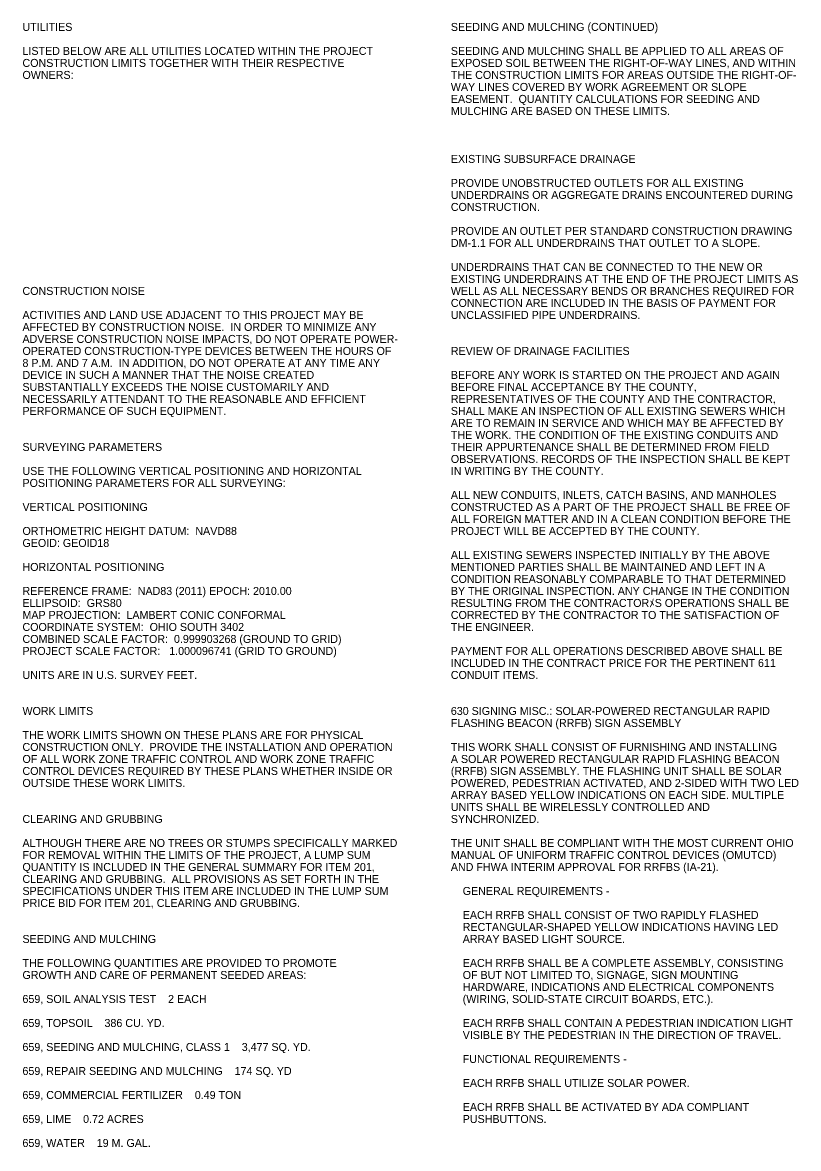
# Model space of a CAD drawing. Extents: x -8.5 to 44.5, y -30.9 to 22.
# Drawn here: x 1.43 to 15.02, y -30.07 to -10.36 of the extents above; entities that cross this region are included whole.
import ezdxf

# ---------------------------------------------------------------- set-up
doc = ezdxf.new("R2010")
doc.units = 0
doc.layers.add('SV_X_Random_Point', color=7, linetype='Continuous')

msp = doc.modelspace()

# ---------------------------------------------------------------- texts
at = {"layer": 'SV_X_Random_Point'}
for s, p in [('UTILITIES', (1.431, -10.511)), ('SEEDING AND MULCHING (CONTINUED)', (8.931, -10.511)), ('LISTED BELOW ARE ALL UTILITIES LOCATED WITHIN THE PROJECT ', (1.431, -10.931)), ('SEEDING AND MULCHING SHALL BE APPLIED TO ALL AREAS OF ', (8.931, -10.931)), ('CONSTRUCTION LIMITS TOGETHER WITH THEIR RESPECTIVE ', (1.431, -11.141)), ('EXPOSED SOIL BETWEEN THE RIGHT-OF-WAY LINES, AND WITHIN ', (8.931, -11.141)), ('OWNERS:', (1.431, -11.351)), ('THE CONSTRUCTION LIMITS FOR AREAS OUTSIDE THE RIGHT-OF-', (8.931, -11.351)), ('WAY LINES COVERED BY WORK AGREEMENT OR SLOPE ', (8.931, -11.561)), ('EASEMENT.  QUANTITY CALCULATIONS FOR SEEDING AND ', (8.931, -11.771)), ('MULCHING ARE BASED ON THESE LIMITS.', (8.931, -11.981)), ('EXISTING SUBSURFACE DRAINAGE', (8.931, -12.821)), ('PROVIDE UNOBSTRUCTED OUTLETS FOR ALL EXISTING ', (8.931, -13.241)), ('UNDERDRAINS OR AGGREGATE DRAINS ENCOUNTERED DURING ', (8.931, -13.451)), ('CONSTRUCTION.', (8.931, -13.661)), ('PROVIDE AN OUTLET PER STANDARD CONSTRUCTION DRAWING ', (8.931, -14.081)), ('DM-1.1 FOR ALL UNDERDRAINS THAT OUTLET TO A SLOPE.', (8.931, -14.291)), ('UNDERDRAINS THAT CAN BE CONNECTED TO THE NEW OR ', (8.931, -14.711)), ('EXISTING UNDERDRAINS AT THE END OF THE PROJECT LIMITS AS ', (8.931, -14.921)), ('CONSTRUCTION NOISE', (1.431, -15.131)), ('WELL AS ALL NECESSARY BENDS OR BRANCHES REQUIRED FOR ', (8.931, -15.131)), ('CONNECTION ARE INCLUDED IN THE BASIS OF PAYMENT FOR ', (8.931, -15.341)), ('ACTIVITIES AND LAND USE ADJACENT TO THIS PROJECT MAY BE ', (1.431, -15.551)), ('UNCLASSIFIED PIPE UNDERDRAINS.', (8.931, -15.551)), ('AFFECTED BY CONSTRUCTION NOISE.  IN ORDER TO MINIMIZE ANY ', (1.431, -15.761)), ('ADVERSE CONSTRUCTION NOISE IMPACTS, DO NOT OPERATE POWER-', (1.431, -15.971)), ('OPERATED CONSTRUCTION-TYPE DEVICES BETWEEN THE HOURS OF ', (1.431, -16.181)), ('REVIEW OF DRAINAGE FACILITIES', (8.931, -16.181)), ('8 P.M. AND 7 A.M.  IN ADDITION, DO NOT OPERATE AT ANY TIME ANY ', (1.431, -16.391)), ('DEVICE IN SUCH A MANNER THAT THE NOISE CREATED ', (1.431, -16.601)), ('BEFORE ANY WORK IS STARTED ON THE PROJECT AND AGAIN ', (8.931, -16.601)), ('SUBSTANTIALLY EXCEEDS THE NOISE CUSTOMARILY AND ', (1.431, -16.811)), ('BEFORE FINAL ACCEPTANCE BY THE COUNTY, ', (8.931, -16.811)), ('NECESSARILY ATTENDANT TO THE REASONABLE AND EFFICIENT ', (1.431, -17.021)), ('REPRESENTATIVES OF THE COUNTY AND THE CONTRACTOR, ', (8.931, -17.021)), ('PERFORMANCE OF SUCH EQUIPMENT.', (1.431, -17.231)), ('SHALL MAKE AN INSPECTION OF ALL EXISTING SEWERS WHICH ', (8.931, -17.231)), ('ARE TO REMAIN IN SERVICE AND WHICH MAY BE AFFECTED BY ', (8.931, -17.441)), ('THE WORK. THE CONDITION OF THE EXISTING CONDUITS AND ', (8.931, -17.651)), ('SURVEYING PARAMETERS', (1.431, -17.861)), ('THEIR APPURTENANCE SHALL BE DETERMINED FROM FIELD ', (8.931, -17.861)), ('OBSERVATIONS. RECORDS OF THE INSPECTION SHALL BE KEPT ', (8.931, -18.071)), ('USE THE FOLLOWING VERTICAL POSITIONING AND HORIZONTAL ', (1.431, -18.281)), ('IN WRITING BY THE COUNTY.', (8.931, -18.281)), ('POSITIONING PARAMETERS FOR ALL SURVEYING:', (1.431, -18.491)), ('ALL NEW CONDUITS, INLETS, CATCH BASINS, AND MANHOLES ', (8.931, -18.701)), ('VERTICAL POSITIONING', (1.431, -18.911)), ('CONSTRUCTED AS A PART OF THE PROJECT SHALL BE FREE OF ', (8.931, -18.911)), ('ALL FOREIGN MATTER AND IN A CLEAN CONDITION BEFORE THE ', (8.931, -19.121)), ('ORTHOMETRIC HEIGHT DATUM:  NAVD88 ', (1.431, -19.331)), ('PROJECT WILL BE ACCEPTED BY THE COUNTY.', (8.931, -19.331)), ('GEOID: GEOID18', (1.431, -19.541)), ('ALL EXISTING SEWERS INSPECTED INITIALLY BY THE ABOVE ', (8.931, -19.751)), ('HORIZONTAL POSITIONING', (1.431, -19.961)), ('MENTIONED PARTIES SHALL BE MAINTAINED AND LEFT IN A ', (8.931, -19.961)), ('CONDITION REASONABLY COMPARABLE TO THAT DETERMINED ', (8.931, -20.171)), ('REFERENCE FRAME:  NAD83 (2011) EPOCH: 2010.00', (1.431, -20.381)), ('BY THE ORIGINAL INSPECTION. ANY CHANGE IN THE CONDITION ', (8.931, -20.381)), ('ELLIPSOID:  GRS80', (1.431, -20.591)), ('RESULTING FROM THE CONTRACTORﾒS OPERATIONS SHALL BE ', (8.931, -20.591)), ('MAP PROJECTION:  LAMBERT CONIC CONFORMAL', (1.431, -20.801)), ('CORRECTED BY THE CONTRACTOR TO THE SATISFACTION OF ', (8.931, -20.801)), ('COORDINATE SYSTEM:  OHIO SOUTH 3402', (1.431, -21.011)), ('THE ENGINEER.', (8.931, -21.011)), ('COMBINED SCALE FACTOR:  0.999903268 (GROUND TO GRID)', (1.431, -21.221)), ('PROJECT SCALE FACTOR:   1.000096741 (GRID TO GROUND)', (1.431, -21.431)), ('PAYMENT FOR ALL OPERATIONS DESCRIBED ABOVE SHALL BE ', (8.931, -21.431)), ('INCLUDED IN THE CONTRACT PRICE FOR THE PERTINENT 611 ', (8.931, -21.641)), ('UNITS ARE IN U.S. SURVEY FEET.', (1.431, -21.851)), ('CONDUIT ITEMS.', (8.931, -21.851)), ('WORK LIMITS', (1.431, -22.481)), ('630 SIGNING MISC.: SOLAR-POWERED RECTANGULAR RAPID', (8.931, -22.481)), ('FLASHING BEACON (RRFB) SIGN ASSEMBLY', (8.931, -22.691)), ('THE WORK LIMITS SHOWN ON THESE PLANS ARE FOR PHYSICAL ', (1.431, -22.901)), ('CONSTRUCTION ONLY.  PROVIDE THE INSTALLATION AND OPERATION ', (1.431, -23.111)), ('THIS WORK SHALL CONSIST OF FURNISHING AND INSTALLING', (8.931, -23.111)), ('OF ALL WORK ZONE TRAFFIC CONTROL AND WORK ZONE TRAFFIC ', (1.431, -23.321)), ('A SOLAR POWERED RECTANGULAR RAPID FLASHING BEACON', (8.931, -23.321)), ('CONTROL DEVICES REQUIRED BY THESE PLANS WHETHER INSIDE OR ', (1.431, -23.531)), ('(RRFB) SIGN ASSEMBLY. THE FLASHING UNIT SHALL BE SOLAR', (8.931, -23.531)), ('OUTSIDE THESE WORK LIMITS.', (1.431, -23.741)), ('POWERED, PEDESTRIAN ACTIVATED, AND 2-SIDED WITH TWO LED', (8.931, -23.741)), ('ARRAY BASED YELLOW INDICATIONS ON EACH SIDE. MULTIPLE', (8.931, -23.951)), ('UNITS SHALL BE WIRELESSLY CONTROLLED AND ', (8.931, -24.161)), ('CLEARING AND GRUBBING', (1.431, -24.371)), ('SYNCHRONIZED.', (8.931, -24.371)), ('ALTHOUGH THERE ARE NO TREES OR STUMPS SPECIFICALLY MARKED ', (1.431, -24.791)), ('THE UNIT SHALL BE COMPLIANT WITH THE MOST CURRENT OHIO', (8.931, -24.791)), ('FOR REMOVAL WITHIN THE LIMITS OF THE PROJECT, A LUMP SUM ', (1.431, -25.001)), ('MANUAL OF UNIFORM TRAFFIC CONTROL DEVICES (OMUTCD)', (8.931, -25.001)), ('QUANTITY IS INCLUDED IN THE GENERAL SUMMARY FOR ITEM 201, ', (1.431, -25.211)), ('AND FHWA INTERIM APPROVAL FOR RRFBS (IA-21).', (8.931, -25.211)), ('CLEARING AND GRUBBING.  ALL PROVISIONS AS SET FORTH IN THE ', (1.431, -25.421)), ('SPECIFICATIONS UNDER THIS ITEM ARE INCLUDED IN THE LUMP SUM ', (1.431, -25.631)), ('    GENERAL REQUIREMENTS -', (8.931, -25.631)), ('PRICE BID FOR ITEM 201, CLEARING AND GRUBBING.', (1.431, -25.841)), ('    EACH RRFB SHALL CONSIST OF TWO RAPIDLY FLASHED', (8.931, -26.051)), ('    RECTANGULAR-SHAPED YELLOW INDICATIONS HAVING LED', (8.931, -26.261)), ('SEEDING AND MULCHING', (1.431, -26.471)), ('    ARRAY BASED LIGHT SOURCE.', (8.931, -26.471)), ('THE FOLLOWING QUANTITIES ARE PROVIDED TO PROMOTE', (1.431, -26.891)), ('    EACH RRFB SHALL BE A COMPLETE ASSEMBLY, CONSISTING', (8.931, -26.891)), ('GROWTH AND CARE OF PERMANENT SEEDED AREAS:', (1.431, -27.101)), ('    OF BUT NOT LIMITED TO, SIGNAGE, SIGN MOUNTING', (8.931, -27.101)), ('    HARDWARE, INDICATIONS AND ELECTRICAL COMPONENTS', (8.931, -27.311)), ('659, SOIL ANALYSIS TEST    2 EACH', (1.431, -27.521)), ('    (WIRING, SOLID-STATE CIRCUIT BOARDS, ETC.).', (8.931, -27.521)), ('659, TOPSOIL    386 CU. YD.', (1.431, -27.941)), ('    EACH RRFB SHALL CONTAIN A PEDESTRIAN INDICATION LIGHT', (8.931, -27.941)), ('    VISIBLE BY THE PEDESTRIAN IN THE DIRECTION OF TRAVEL.', (8.931, -28.151)), ('659, SEEDING AND MULCHING, CLASS 1    3,477 SQ. YD.', (1.431, -28.361)), ('    FUNCTIONAL REQUIREMENTS -', (8.931, -28.571)), ('659, REPAIR SEEDING AND MULCHING    174 SQ. YD', (1.431, -28.781)), ('    EACH RRFB SHALL UTILIZE SOLAR POWER.', (8.931, -28.991)), ('659, COMMERCIAL FERTILIZER    0.49 TON', (1.431, -29.201)), ('    EACH RRFB SHALL BE ACTIVATED BY ADA COMPLIANT', (8.931, -29.411)), ('659, LIME    0.72 ACRES', (1.431, -29.621)), ('    PUSHBUTTONS.', (8.931, -29.621)), ('659, WATER    19 M. GAL.', (1.431, -30.041))]:
    msp.add_text(s, height=0.14, dxfattribs=at).set_placement(p)

doc.saveas('drawing.dxf')
